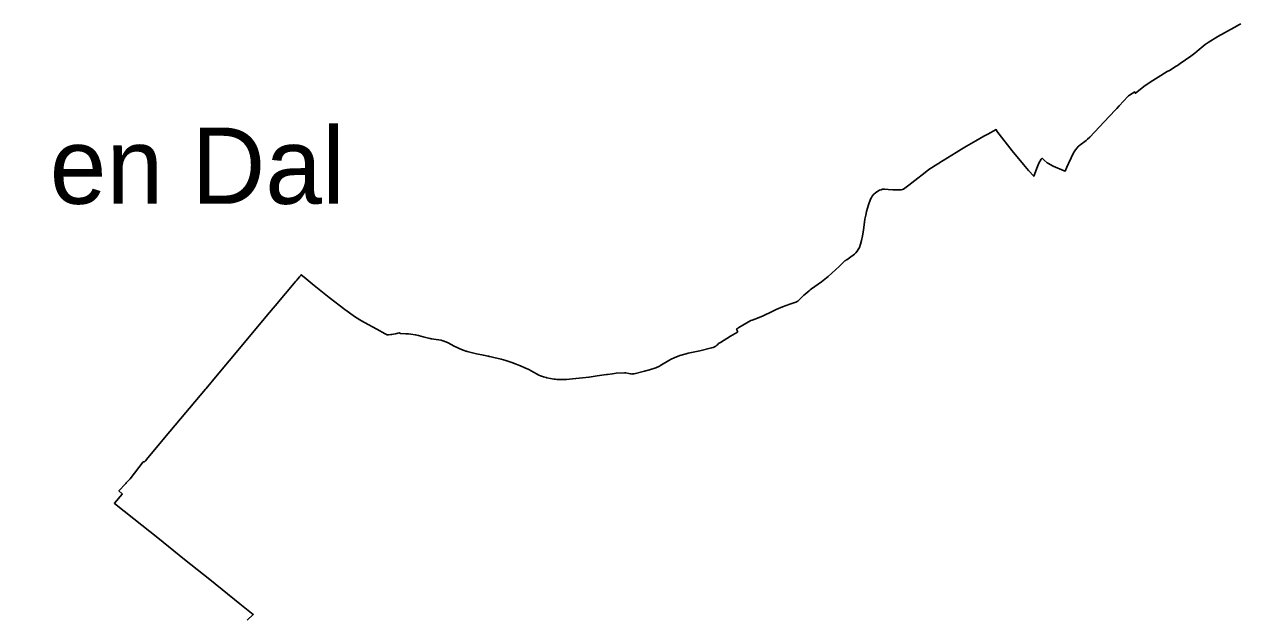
# Model space of a CAD drawing. Extents: x 113371 to 291721, y 393993 to 520143.
# Drawn here: x 192843 to 200812, y 425533 to 429408 of the extents above; entities that cross this region are included whole.
import ezdxf

# ---------------------------------------------------------------- set-up
doc = ezdxf.new("R2010")
doc.units = 0
doc.layers.add('Default', color=7, linetype='Continuous')
doc.layers.add('plaatsnamen', color=7, linetype='Continuous')

msp = doc.modelspace()

# ---------------------------------------------------------------- linework, layer by layer
at = {"layer": 'Default'}
for points in [[(199730.085625, 428584.3025), (199740.615625, 428599.1525), (199746.885625, 428606.6825), (199748.935625, 428609.7425), (199755.455625, 428614.3025), (199767.595625, 428623.0425), (199791.365625, 428640.0025), (199799.605625, 428646.4725), (199809.245625, 428654.4025), (199824.405625, 428669.0125), (199950.555625, 428803.2625), (199993.095625, 428848.5325), (199993.755625, 428849.3425), (199996.195625, 428852.3225), (199999.885625, 428856.8325), (200015.185625, 428873.6225), (200071.695625, 428935.6225), (200077.295625, 428939.5125), (200084.015625, 428944.1925), (200117.465625, 428964.1825), (200122.125625, 428956.1325), (200186.375625, 429006.9825), (200236.405625, 429038.5525), (200270.575625, 429060.7225), (200329.435625, 429097.7225), (200344.325625, 429105.8925), (200389.375625, 429132.9125), (200398.015625, 429138.2725), (200415.875625, 429149.8425), (200485.075625, 429199.9725), (200510.545625, 429218.8425), (200525.575625, 429231.0625), (200552.095625, 429253.2725), (200579.765625, 429275.1425), (200599.305625, 429288.7025), (200661.135625, 429328.4525), (200769.535625, 429387.3625), (200802.975625, 429405.4925)], [(200802.975625, 429405.4925), (200811.685625, 429410.6625)], [(198602.125625, 428327.5925), (198636.925625, 428353.2925), (198677.315625, 428384.5625), (198743.765625, 428437.1325), (198768.605625, 428456.4825), (198828.645625, 428492.8125), (198833.675625, 428496.0325), (198835.195625, 428497.0125), (198946.935625, 428568.4625), (198982.645625, 428589.8625), (199014.565625, 428608.3825), (199076.755625, 428644.1125), (199128.835625, 428674.0025), (199156.195625, 428688.8625), (199210.145625, 428717.7925), (199211.525625, 428714.6725), (199211.805625, 428714.0125), (199214.455625, 428708.0425), (199315.635625, 428578.8925), (199388.555625, 428488.2025), (199421.845625, 428450.4225), (199456.075625, 428411.5925), (199480.225625, 428475.1125), (199489.805625, 428497.5625), (199505.665625, 428523.4725), (199511.665625, 428529.5525), (199523.285625, 428518.3425), (199544.105625, 428500.7625), (199548.025625, 428497.4525), (199583.385625, 428477.2725), (199655.895625, 428447.4625), (199661.715625, 428445.3025), (199672.845625, 428471.8025), (199683.905625, 428496.0125), (199700.115625, 428533.0625), (199710.375625, 428552.5425), (199721.795625, 428571.5725), (199730.085625, 428584.3025)], [(198219.785625, 427857.9925), (198222.465625, 427860.6025), (198224.645625, 427862.7225), (198226.335625, 427864.3325), (198228.405625, 427866.3025), (198229.465625, 427865.4725), (198230.785625, 427864.3625), (198249.005625, 427878.2925), (198281.295625, 427902.5525), (198289.925625, 427910.2525), (198298.845625, 427920.3325), (198306.615625, 427931.1725), (198313.415625, 427944.3925), (198321.135625, 427967.5025), (198327.985625, 427991.4925), (198334.725625, 428021.5825), (198340.535625, 428058.1525), (198350.425625, 428130.4025), (198354.975625, 428156.6925), (198360.605625, 428180.5225), (198374.455625, 428225.0825), (198387.165625, 428262.8725), (198392.365625, 428273.5725), (198398.005625, 428282.5225), (198409.195625, 428295.0725), (198418.315625, 428303.6425), (198419.275625, 428304.3125), (198433.965625, 428314.5225), (198445.985625, 428320.2925), (198456.705625, 428324.1125), (198466.185625, 428326.9125), (198479.195625, 428327.0225), (198502.185625, 428325.1825), (198533.205625, 428323.1825), (198572.995625, 428322.8625), (198587.755625, 428323.7125), (198595.495625, 428324.7525), (198602.125625, 428327.5925)], [(197364.885625, 427294.9025), (197368.685625, 427296.3525), (197373.015625, 427299.5825), (197376.325625, 427301.3625), (197380.855625, 427304.6125), (197384.585625, 427307.9725), (197391.315625, 427315.6425), (197402.885625, 427323.2225), (197470.005625, 427363.4325), (197514.835625, 427390.3625), (197515.985625, 427392.3025), (197514.725625, 427397.5225), (197509.215625, 427410.4225), (197513.375625, 427413.0025), (197518.235625, 427416.0125), (197524.975625, 427420.2025), (197603.405625, 427465.8725), (197610.255625, 427469.0425), (197646.835625, 427482.4525), (197683.665625, 427497.2825), (197742.795625, 427525.9125), (197769.035625, 427538.6225), (197810.995625, 427556.3425), (197858.225625, 427573.4425), (197896.705625, 427587.3725), (197909.695625, 427594.3025), (197919.895625, 427603.2825), (197950.755625, 427632.2325), (197959.465625, 427639.8225), (197985.505625, 427662.2925), (197987.355625, 427663.7825), (197992.175625, 427667.6525), (198001.085625, 427674.4425), (198064.425625, 427719.3825), (198110.225625, 427755.6125), (198180.495625, 427819.7725), (198219.095625, 427857.3325), (198219.785625, 427857.9925)], [(193434.645625, 426267.6725), (193432.875625, 426269.2225), (193483.015625, 426328.5625), (193484.695625, 426330.5625), (193462.205625, 426349.7925), (193507.375625, 426398.7025), (193510.975625, 426402.5925), (193536.015625, 426429.7125), (193622.335625, 426540.2225), (193630.795625, 426540.9425), (193633.965625, 426544.7225), (193636.385625, 426547.6125), (193652.435625, 426566.7725), (193796.925625, 426739.2325), (194030.265625, 427017.7525), (194034.125625, 427022.3625), (194106.285625, 427108.4925), (194108.455625, 427111.0825), (194139.765625, 427148.4625), (194185.105625, 427202.5825), (194187.825625, 427205.8225), (194425.755625, 427489.8325), (194473.455625, 427546.7625), (194486.335625, 427562.1325), (194622.355625, 427724.4925), (194623.415625, 427725.7525), (194628.025625, 427731.2625), (194645.605625, 427752.2525), (194652.315625, 427760.2525), (194657.445625, 427766.3025), (194677.115625, 427750.3625), (194741.485625, 427696.5225), (194839.495625, 427617.9325), (194941.695625, 427538.3125), (195012.435625, 427488.3225), (195052.095625, 427464.9925), (195072.355625, 427453.7225), (195152.475625, 427409.1125)], [(195152.475625, 427409.1125), (195205.995625, 427380.4325), (195214.625625, 427376.1825), (195220.315625, 427373.9625), (195224.975625, 427372.9625), (195229.525625, 427372.9225), (195243.855625, 427374.1425), (195248.635625, 427374.5525), (195274.395625, 427380.2525), (195283.585625, 427382.2825), (195289.995625, 427383.7025), (195298.555625, 427385.5925), (195302.175625, 427383.9825), (195308.015625, 427381.1125), (195342.795625, 427380.2725), (195360.485625, 427379.4225), (195375.825625, 427377.9925), (195403.595625, 427373.7225), (195425.435625, 427368.9925), (195455.375625, 427360.8825), (195499.885625, 427349.0025), (195502.255625, 427348.3725), (195507.225625, 427347.4025), (195513.485625, 427346.1825), (195525.395625, 427345.2625), (195572.975625, 427337.7725), (195584.395625, 427334.7025), (195585.365625, 427334.3325), (195590.545625, 427332.3525), (195594.085625, 427330.9825), (195619.375625, 427320.0325), (195659.435625, 427299.4825), (195682.145625, 427288.2325), (195695.535625, 427281.6025), (195725.285625, 427270.3425), (195735.675625, 427266.9925), (195739.545625, 427265.7425), (195743.405625, 427264.4925)], [(196395.165625, 427080.7225), (196434.655625, 427084.3825), (196499.675625, 427091.0825), (196541.215625, 427096.2025), (196542.725625, 427096.4125), (196569.415625, 427100.2425), (196596.605625, 427104.5225), (196656.725625, 427113.1025), (196662.695625, 427113.8325), (196696.455625, 427117.9225), (196719.665625, 427120.7425), (196774.395625, 427124.2225), (196783.295625, 427122.9925), (196802.785625, 427119.4025), (196803.435625, 427119.2825), (196816.005625, 427116.7225), (196822.595625, 427116.0525), (196830.415625, 427116.5525), (196838.965625, 427117.9825), (196906.505625, 427134.6325), (196939.485625, 427143.4525), (196980.205625, 427157.7125), (197005.175625, 427168.5025), (197010.395625, 427171.7325), (197011.905625, 427172.6625), (197013.475625, 427173.6425), (197017.835625, 427176.3425), (197065.145625, 427205.3625), (197081.405625, 427213.8525), (197101.365625, 427222.8825), (197137.095625, 427237.0125), (197178.455625, 427248.6225), (197192.845625, 427252.6525), (197268.435625, 427268.5325), (197345.915625, 427287.5825), (197355.455625, 427290.9625), (197364.395625, 427294.7225), (197364.885625, 427294.9025)], [(195743.405625, 427264.4925), (195762.625625, 427259.4825), (195805.705625, 427249.2025), (195850.455625, 427239.4225), (195880.715625, 427232.8625), (195880.985625, 427232.8025), (195882.515625, 427232.4925), (195883.725625, 427232.2525), (195887.745625, 427231.4425), (195890.455625, 427230.8925), (195893.385625, 427230.3025), (195917.845625, 427225.3625), (195967.105625, 427213.6425), (195998.535625, 427204.1425), (196035.805625, 427191.7225), (196065.505625, 427181.1225), (196087.235625, 427172.7225), (196094.145625, 427170.0425), (196122.375625, 427157.0025), (196148.345625, 427144.8725), (196178.905625, 427127.9525), (196202.295625, 427114.4725), (196214.335625, 427109.0225), (196223.595625, 427105.1625), (196231.855625, 427101.8125), (196243.895625, 427098.0125), (196261.185625, 427092.7225), (196261.715625, 427092.6125), (196265.605625, 427091.8125), (196290.335625, 427086.7725), (196300.655625, 427084.8625), (196313.185625, 427082.9825), (196321.635625, 427081.6925), (196322.735625, 427081.5125), (196331.375625, 427080.0825), (196342.095625, 427079.4125), (196375.825625, 427079.3225), (196395.165625, 427080.7225)], [(194303.175625, 425502.8325), (194342.195625, 425540.5525), (194255.195625, 425611.0025), (194058.035625, 425768.9825), (193892.935625, 425900.8125), (193716.845625, 426042.3925), (193560.775625, 426167.1325), (193434.645625, 426267.6725)]]:
    msp.add_lwpolyline(points, dxfattribs=at)

# ---------------------------------------------------------------- texts
at = {"layer": 'plaatsnamen'}
msp.add_text('Berg en Dal', height=500, dxfattribs=at).set_placement((191411.231668, 428231.335917))

doc.saveas('drawing.dxf')
